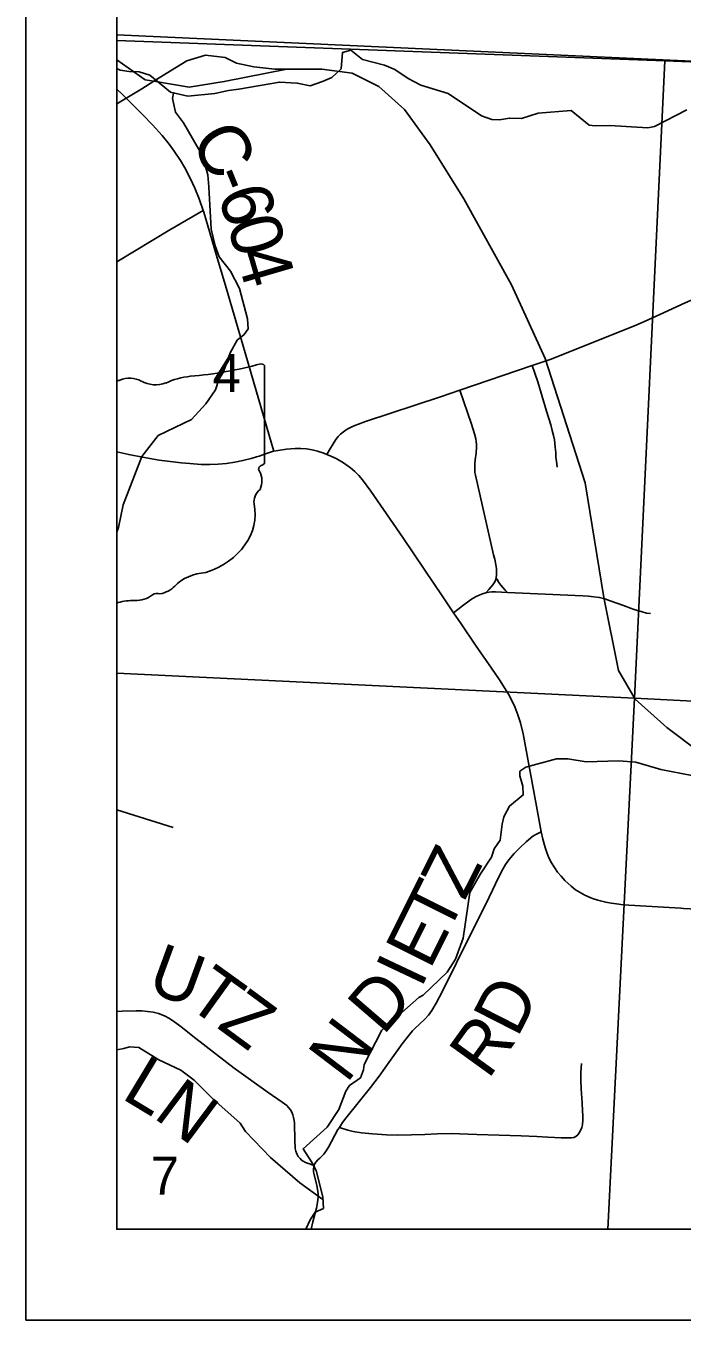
# Model space of a CAD drawing. Extents: x 0 to 34, y 0 to 22.
# Drawn here: x 2 to 2.723, y 14 to 15.425 of the extents above; entities that cross this region are included whole.
import ezdxf

# ---------------------------------------------------------------- set-up
doc = ezdxf.new("R2010")
doc.units = 0
for name, color, linetype in [('GM_X_County_Road', 7, 'Continuous'), ('GM_X_County_Road_Text', 7, 'Continuous'), ('GM_X_Minor_River', 7, 'Continuous'), ('GM_X_Rail_Line', 7, 'Continuous'), ('GM_X_Section', 7, 'Continuous'), ('GM_X_Section_Text', 7, 'Continuous'), ('GM_X_State_Route', 7, 'Continuous'), ('GM_X_Township_Road', 7, 'Continuous'), ('GM_X_Township_Text', 7, 'Continuous'), ('GM_X_Unincorporated_Text', 7, 'Continuous'), ('SH_Data', 7, 'Continuous')]:
    doc.layers.add(name, color=color, linetype=linetype)

msp = doc.modelspace()

# ---------------------------------------------------------------- linework, layer by layer
at = {"layer": 'GM_X_County_Road'}
for points in [[(2.1953, 15.2216), (2.1907, 15.2346), (2.1861, 15.2462), (2.1809, 15.2575), (2.1751, 15.2686), (2.1703, 15.2766), (2.1634, 15.287), (2.1579, 15.2946), (2.15, 15.3043), (2.1396, 15.3159), (2.1288, 15.3271), (2.1066, 15.349), (2.1, 15.3555)], [(2.1, 15.1653), (2.1587, 15.2004), (2.1953, 15.2216)], [(2.2731, 14.9566), (2.2709, 14.9639), (2.239, 15.0737), (2.2293, 15.1065), (2.2207, 15.1364), (2.2099, 15.1721), (2.2005, 15.205), (2.1959, 15.2199), (2.1953, 15.2216)], [(2.3452, 14.212), (2.3486, 14.2175), (2.3523, 14.2224), (2.3796, 14.2562), (2.389, 14.2686), (2.4016, 14.2863), (2.4143, 14.304), (2.4199, 14.3113), (2.4259, 14.3183), (2.428, 14.3205), (2.4393, 14.3312), (2.4435, 14.3359), (2.4472, 14.341), (2.4519, 14.349), (2.459, 14.3629), (2.4744, 14.3934), (2.5102, 14.4657), (2.5209, 14.4881), (2.5251, 14.4964), (2.5283, 14.5016), (2.5319, 14.5066), (2.5378, 14.5137), (2.5442, 14.5204), (2.5509, 14.5267), (2.5582, 14.5329), (2.5622, 14.5349), (2.5675, 14.5376)], [(2.3175, 14.1703), (2.3101, 14.1727), (2.3081, 14.1735), (2.3055, 14.175), (2.3036, 14.1762), (2.3019, 14.1778), (2.2999, 14.1802), (2.2984, 14.1829), (2.2973, 14.1858), (2.2967, 14.1889), (2.2962, 14.1982), (2.2957, 14.2168), (2.2954, 14.2199), (2.2949, 14.223), (2.2941, 14.226), (2.2929, 14.2288), (2.2913, 14.2315), (2.2894, 14.234), (2.2872, 14.2362), (2.2823, 14.2399), (2.2669, 14.2504), (2.2295, 14.2775), (2.1871, 14.31), (2.1709, 14.3228), (2.1626, 14.3291), (2.1574, 14.3325), (2.1534, 14.3348), (2.149, 14.3365), (2.146, 14.3375), (2.14, 14.3389), (2.1338, 14.3398), (2.1276, 14.3404), (2.1214, 14.3405), (2.1059, 14.34), (2.1, 14.3397)], [(2.3175, 14.1703), (2.3179, 14.1717), (2.3194, 14.174), (2.3214, 14.1763), (2.3237, 14.1783), (2.3283, 14.1827), (2.3301, 14.1852), (2.3334, 14.1905), (2.3437, 14.2097), (2.3452, 14.212)], [(2.3141, 14.1), (2.3161, 14.1081), (2.32, 14.1231), (2.3212, 14.1293), (2.3218, 14.1356), (2.3218, 14.1387), (2.3215, 14.1419), (2.3204, 14.1481), (2.3174, 14.1602), (2.3169, 14.1632), (2.3168, 14.1661), (2.3171, 14.1689), (2.3175, 14.1703)]]:
    msp.add_lwpolyline(points, dxfattribs=at)
at = {"layer": 'GM_X_Minor_River'}
for points in [[(2.1, 15.3779), (2.104, 15.3763), (2.1138, 15.3748), (2.1248, 15.3745), (2.1365, 15.3707), (2.1593, 15.3519), (2.1783, 15.3478), (2.2081, 15.3506), (2.2232, 15.3537), (2.2346, 15.3553), (2.2792, 15.3631), (2.2989, 15.3621), (2.3129, 15.3591), (2.3265, 15.3638), (2.337, 15.368), (2.3472, 15.3776), (2.3486, 15.3958), (2.3577, 15.3981), (2.3706, 15.3879), (2.3948, 15.3816), (2.4062, 15.3771), (2.421, 15.3669), (2.4351, 15.3598), (2.465, 15.3505), (2.5018, 15.326), (2.5132, 15.3219), (2.5215, 15.3215), (2.5325, 15.3235), (2.5457, 15.3232), (2.5642, 15.329), (2.6005, 15.3318), (2.6203, 15.3156), (2.6271, 15.3149), (2.643, 15.3154), (2.685, 15.3129), (2.6921, 15.3141), (2.728, 15.3325)], [(2.1627, 15.3511), (2.1613, 15.345), (2.1647, 15.3299), (2.1735, 15.3181), (2.1941, 15.2826), (2.2003, 15.2609), (2.2015, 15.2477), (2.204, 15.201), (2.2083, 15.1828), (2.2129, 15.1706), (2.2254, 15.1548), (2.2354, 15.1358), (2.2442, 15.1025), (2.2447, 15.0914), (2.2405, 15.0853), (2.2326, 15.0788), (2.2251, 15.0651), (2.2177, 15.0442), (2.2124, 15.0358), (2.2087, 15.0244), (2.1982, 15.0088), (2.1824, 14.9916), (2.1458, 14.9739), (2.1278, 14.9507), (2.1072, 14.8978), (2.1021, 14.8727), (2.1, 14.8675)], [(2.3084, 14.1), (2.3084, 14.1), (2.3129, 14.1103), (2.3185, 14.1187), (2.3276, 14.1229), (2.3271, 14.1358), (2.3198, 14.1646), (2.3145, 14.1744), (2.3053, 14.1884), (2.3317, 14.2125), (2.3448, 14.2319), (2.3523, 14.2521), (2.3564, 14.2582), (2.3685, 14.2666), (2.3718, 14.2757), (2.3725, 14.2814), (2.392, 14.3191), (2.4327, 14.355), (2.4376, 14.3577), (2.4639, 14.3829), (2.4733, 14.3974), (2.4815, 14.4206), (2.4888, 14.4708), (2.5008, 14.4913), (2.5128, 14.5096), (2.5158, 14.5188), (2.5222, 14.5283), (2.5244, 14.5461), (2.5262, 14.5541), (2.5326, 14.5659), (2.5477, 14.5782), (2.5472, 14.588), (2.5438, 14.5994), (2.5441, 14.6043), (2.5505, 14.6089), (2.5842, 14.6179), (2.597, 14.6179), (2.6171, 14.6146), (2.653, 14.6156), (2.6719, 14.6142), (2.6992, 14.6063), (2.7333, 14.5997)], [(2.3272, 14.1329), (2.3017, 14.1512), (2.2694, 14.1791), (2.242, 14.2078), (2.2359, 14.2169), (2.2059, 14.2437), (2.1854, 14.2641), (2.1706, 14.275), (2.1463, 14.2867), (2.1243, 14.3002), (2.1141, 14.3009), (2.108, 14.299), (2.1, 14.2976)]]:
    msp.add_lwpolyline(points, dxfattribs=at)
at = {"layer": 'GM_X_Rail_Line'}
for points in [[(2.1, 18.4819), (2.1, 15.4153), (3.9123, 15.3323), (3.9451, 15.3313), (3.973, 15.329), (4.0133, 15.3262), (4.0257, 15.3251), (4.0381, 15.324), (4.0782, 15.3206), (4.1061, 15.3185), (4.1743, 15.3141), (4.1849, 15.3132), (4.1956, 15.3121), (4.1973, 15.3118), (5.1044, 15.2759), (5.2458, 15.271), (5.4522, 15.2638), (5.479, 15.731), (5.4821, 15.8189)], [(2.141, 15.364), (2.1545, 15.3724), (2.1774, 15.3864), (2.1977, 15.3927), (2.2193, 15.3902), (2.232, 15.3838), (2.2511, 15.38), (2.274, 15.3775), (2.2875, 15.3775)], [(2.141, 15.364), (2.1312, 15.3657), (2.1, 15.3875)], [(2.2875, 15.3775), (2.2185, 15.3637), (2.1799, 15.3576), (2.141, 15.364)], [(2.2875, 15.3775), (2.3007, 15.3775), (2.3261, 15.3775), (2.3593, 15.3731), (2.3886, 15.3581), (2.4169, 15.3329), (2.4454, 15.2942), (2.4822, 15.2347), (2.5347, 15.14), (2.5719, 15.0586), (2.6161, 14.9219), (2.6364, 14.7957), (2.6527, 14.7151), (2.671, 14.6836), (2.7058, 14.6525), (2.777, 14.599)], [(2.1, 15.3393), (2.1278, 15.3558), (2.141, 15.364)]]:
    msp.add_lwpolyline(points, dxfattribs=at)
msp.add_lwpolyline([(2.1, 15.4153), (2.1, 14.1), (6.4223, 14.1), (6.4607, 14.8895), (6.4764, 15.22), (6.2705, 15.2288), (5.4522, 15.2638), (5.2458, 15.271), (5.1044, 15.2759), (4.1973, 15.3118), (4.1956, 15.3121), (4.1849, 15.3132), (4.1743, 15.3141), (4.1061, 15.3185), (4.0782, 15.3206), (4.0381, 15.324), (4.0257, 15.3251), (4.0133, 15.3262), (3.973, 15.329), (3.9451, 15.3313), (3.9123, 15.3323)], close=True, dxfattribs=at)
at = {"layer": 'GM_X_Section'}
msp.add_lwpolyline([(2.9571, 15.3766), (3.7314, 15.3424), (3.7021, 14.6318), (2.6704, 14.6848), (2.7035, 15.3864)], close=True, dxfattribs=at)
at = {"layer": 'GM_X_State_Route'}
for points in [[(2.1, 14.9561), (2.1133, 14.953), (2.1285, 14.95), (2.1469, 14.947), (2.1653, 14.9445), (2.1711, 14.9439)], [(2.1711, 14.9439), (2.1807, 14.943), (2.1931, 14.9421), (2.2024, 14.9419), (2.2116, 14.9423), (2.2208, 14.9432), (2.23, 14.9446), (2.2391, 14.9463), (2.248, 14.9487), (2.2539, 14.9505), (2.2569, 14.9513), (2.2627, 14.9535), (2.2716, 14.9562), (2.2731, 14.9566), (2.2777, 14.9576), (2.287, 14.9589), (2.2964, 14.9596), (2.3027, 14.9596), (2.3089, 14.9592), (2.3152, 14.9583), (2.3213, 14.9568), (2.3272, 14.9549), (2.3315, 14.9532)], [(2.3315, 14.9532), (2.336, 14.9514), (2.3416, 14.9487), (2.3497, 14.9439), (2.3574, 14.9385), (2.3622, 14.9345), (2.3667, 14.9301), (2.3707, 14.9253), (2.3799, 14.9127), (2.4151, 14.8616)], [(2.4151, 14.8616), (2.4394, 14.8257), (2.4585, 14.7974), (2.471, 14.7788), (2.4793, 14.7665), (2.495, 14.7433), (2.5126, 14.7177), (2.5215, 14.705), (2.5314, 14.6892), (2.5345, 14.6837), (2.5385, 14.6752), (2.5419, 14.6665), (2.5446, 14.6575), (2.5475, 14.6454), (2.5623, 14.566), (2.5666, 14.5415), (2.5675, 14.5376)], [(2.5675, 14.5376), (2.5692, 14.5294), (2.5717, 14.5205), (2.5737, 14.5147), (2.576, 14.509), (2.5788, 14.5035), (2.582, 14.4983), (2.5856, 14.4933), (2.5895, 14.4886), (2.5937, 14.4841), (2.6004, 14.4777), (2.6051, 14.4739), (2.6103, 14.4707), (2.6157, 14.4678), (2.6213, 14.4652), (2.6241, 14.4642), (2.6299, 14.4623), (2.6328, 14.4615), (2.6386, 14.4601), (2.6445, 14.4591), (2.6504, 14.4583), (2.6577, 14.4572), (2.7211, 14.4534)], [(2.7211, 14.4534), (2.7243, 14.4533), (2.8855, 14.4452)]]:
    msp.add_lwpolyline(points, dxfattribs=at)
at = {"layer": 'GM_X_Township_Road'}
for p, q in [((2.478, 15.024), (2.5577, 15.0512)), ((2.5303, 14.8011), (2.6135, 14.7975)), ((2.1, 14.5619), (2.1623, 14.5424))]:
    msp.add_line(p, q, dxfattribs=at)
for points in [[(2.5577, 15.0512), (2.5773, 15.0578), (2.5878, 15.0617), (2.5976, 15.0656), (2.6721, 15.0956), (2.6861, 15.1016), (2.6982, 15.1073), (2.7259, 15.12), (2.732, 15.1227), (2.7399, 15.1257), (2.7452, 15.1275), (2.7478, 15.1282), (2.7509, 15.129), (2.754, 15.1294), (2.7569, 15.1296), (2.7593, 15.1296), (2.7659, 15.1295), (2.774, 15.129), (2.7856, 15.1276), (2.8092, 15.1244), (2.8317, 15.1207), (2.838, 15.1195)], [(2.5851, 14.9392), (2.5842, 14.9456), (2.5838, 14.9497), (2.5836, 14.9529), (2.5835, 14.9553), (2.5829, 14.9613), (2.5826, 14.9652), (2.582, 14.9693), (2.581, 14.974), (2.5797, 14.9796), (2.578, 14.9857), (2.5733, 15.0006), (2.5637, 15.033), (2.5577, 15.0512)], [(2.3663, 14.9864), (2.3741, 14.9893), (2.4567, 15.0167), (2.478, 15.024)], [(2.5179, 14.817), (2.5182, 14.8208), (2.5183, 14.8241), (2.5181, 14.8277), (2.5175, 14.8314), (2.5163, 14.8377), (2.5151, 14.8425), (2.495, 14.9304), (2.4946, 14.9334), (2.4943, 14.9363), (2.4944, 14.9393), (2.4946, 14.9431), (2.4949, 14.9471), (2.496, 14.9545), (2.4963, 14.961), (2.4962, 14.9641), (2.4959, 14.9672), (2.4955, 14.9703), (2.4942, 14.9757), (2.4908, 14.9866), (2.478, 15.024)], [(2.3315, 14.9532), (2.3345, 14.9583), (2.3385, 14.9649), (2.3415, 14.9696), (2.344, 14.9728), (2.3465, 14.9753), (2.3485, 14.977), (2.3512, 14.9791), (2.3538, 14.9809), (2.3589, 14.9836), (2.3624, 14.985), (2.3663, 14.9864)], [(2.5064, 14.8009), (2.5099, 14.8043), (2.5122, 14.8071), (2.5141, 14.8095), (2.5158, 14.8119), (2.517, 14.8143), (2.5179, 14.817)], [(2.5303, 14.8011), (2.5278, 14.8038), (2.5252, 14.8066), (2.5231, 14.8092), (2.5209, 14.8122), (2.5189, 14.8153), (2.5179, 14.817)], [(2.471, 14.7788), (2.4758, 14.7825), (2.4808, 14.7863), (2.4908, 14.7936), (2.4934, 14.7952), (2.4959, 14.7967), (2.4991, 14.7983), (2.5028, 14.7998), (2.5064, 14.8009)], [(2.5064, 14.8009), (2.51, 14.8015), (2.513, 14.8017), (2.5171, 14.8017), (2.5303, 14.8011)], [(2.6135, 14.7975), (2.6195, 14.7971), (2.6255, 14.7965), (2.6317, 14.7956), (2.6377, 14.7941), (2.6436, 14.7921), (2.6581, 14.7867), (2.6659, 14.7838)], [(2.6659, 14.7838), (2.6698, 14.7824), (2.6787, 14.7797), (2.6835, 14.7785), (2.6878, 14.778)], [(2.3452, 14.212), (2.3545, 14.2091), (2.3605, 14.2077), (2.3696, 14.2063), (2.3819, 14.2049), (2.3973, 14.2038), (2.4096, 14.2035), (2.4246, 14.204), (2.4392, 14.2045), (2.4528, 14.2052), (2.4683, 14.2053), (2.4776, 14.2052), (2.4965, 14.2045), (2.5212, 14.2036), (2.5454, 14.203), (2.5628, 14.2021), (2.5747, 14.2014), (2.5896, 14.2007), (2.5954, 14.2005), (2.5979, 14.2005), (2.6008, 14.2005), (2.6033, 14.2011), (2.6056, 14.2021), (2.6077, 14.204), (2.6095, 14.2063), (2.6109, 14.2089), (2.6123, 14.2122), (2.6129, 14.2149), (2.6133, 14.2204), (2.6134, 14.2252), (2.6131, 14.2299), (2.6126, 14.2391), (2.6115, 14.2545), (2.6112, 14.2637), (2.6113, 14.273), (2.6119, 14.2824)]]:
    msp.add_lwpolyline(points, dxfattribs=at)
at = {"layer": 'GM_X_Township_Text'}
msp.add_line((2.1, 15.0341), (2.1, 14.7896), dxfattribs=at)
msp.add_lwpolyline([(2.2629, 14.9448), (2.2629, 14.9448), (2.2629, 14.9448), (2.2629, 15.0497)], dxfattribs=at)
for centre, major_axis, start_param, end_param in [((2.1455, 15.3174), (0.3495, 0), 4.814394, 5.042369), ((2.2592, 15.0499), (0.00367, 0), 6.197627, 7.989034), ((2.0985, 15.0426), (0.0107, 0), 4.851348, 5.185415), ((2.1142, 15.0194), (0.0222, 0), 0.950623, 2.079405), ((2.1901, 14.9834), (0.0703, 0), 1.699012, 2.107814), ((2.1429, 15.0512), (0.0267, 0), 4.08156, 5.145723), ((2.262, 14.9371), (0.00568, 0), 1.883978, 3.671073), ((2.2259, 14.9239), (0.0341, 0), 5.934695, 6.695948), ((2.259, 14.9444), (0.00393, 0), 5.05454, 6.418171), ((2.276, 14.901), (0.0248, 0), 2.387724, 3.262537), ((2.1651, 14.8877), (0.0874, 0), 5.101753, 6.440018), ((2.2019, 14.7848), (0.0479, 0), 1.647645, 2.488434), ((2.1413, 14.8216), (0.0282, 0), 4.937069, 5.64225), ((2.1167, 14.7593), (0.0412, 0), 1.495662, 1.94098), ((2.1203, 14.8135), (0.0267, 0), 4.691044, 5.507374), ((2.1445, 14.7941), (0.00752, 0), 1.147584, 2.315152), ((2.0877, 14.8284), (0.0501, 0), 4.960327, 4.996735)]:
    msp.add_ellipse(centre, major_axis=major_axis, ratio=0.8, start_param=start_param, end_param=end_param, dxfattribs=at)
at = {"layer": 'GM_X_Unincorporated_Text'}
for points in [[(2.1, 15.409), (2.1, 14.7124), (2.6704, 14.6848), (2.7035, 15.3864)], [(2.1, 14.7124), (2.1, 14.1), (2.641, 14.1), (2.6704, 14.6848)], [(2.641, 14.1), (3.681, 14.1), (3.7021, 14.6318), (2.6704, 14.6848)]]:
    msp.add_lwpolyline(points, close=True, dxfattribs=at)
at = {"layer": 'SH_Data'}
for p, q in [((2, 21), (2, 14)), ((2.1, 20.9), (2.1, 14.1)), ((2.1, 14.1), (8.9, 14.1)), ((2.1, 14.1), (2.1, 14.1)), ((2, 14), (9, 14))]:
    msp.add_line(p, q, dxfattribs=at)

# ---------------------------------------------------------------- texts
at = {"layer": 'GM_X_County_Road_Text'}
for s, rotation, p in [('C', 299.5318, (2.1802, 15.299)), ('-', 292.1517, (2.2022, 15.2604)), ('6', 287.9852, (2.2106, 15.24)), ('0', 286.1681, (2.2212, 15.2075)), ('4', 286.2642, (2.2308, 15.174)), ('Z', 63.2433, (2.483, 14.4608)), ('T', 63.3717, (2.4639, 14.4229)), ('E', 63.3717, (2.4449, 14.3849)), ('U', 339.9095, (2.1315, 14.3626)), ('I', 64.7328, (2.4351, 14.3641)), ('T', 324.271, (2.1749, 14.3474)), ('D', 49.2, (2.3934, 14.3124)), ('Z', 323.6418, (2.2092, 14.3226)), ('D', 63.026, (2.5412, 14.3098)), ('N', 52.7877, (2.3532, 14.2595)), ('R', 54.1769, (2.509, 14.264)), ('L', 328.9187, (2.1039, 14.2448)), ('N', 323.2999, (2.1391, 14.2237))]:
    msp.add_text(s, height=0.0568, rotation=rotation, dxfattribs=at).set_placement(p)
at = {"layer": 'GM_X_Section_Text'}
for s, p in [('4', (2.2055, 15.022)), ('7', (2.1375, 14.138))]:
    msp.add_text(s, height=0.0419, rotation=0, dxfattribs=at).set_placement(p)

doc.saveas('drawing.dxf')
